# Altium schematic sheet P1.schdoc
size 297 x 209 mm; Symbol: Drawing-Symbol_A4; Company: 嘉立创EDA; Version: V1.0; Page Size: A4; @Project Name: Arduinoi时钟; @Update Date: 2026-04-30; @Create Date: 2026-04-30; Device: Drawing-Symbol_A4; @Board Name: Board1; @Page Name: P1; @Create Time: 08:59:18; @Page Count: 1; @Page No: 1; @Schematic Name: Schematic1; @Update Time: 08:59:18; @Assembly Variant: Basic; Border: 1; Title Block Position: 3; Size: A4; Width: 1170; Height: 825; Region Start: 1; X Region Count: 6; Y Region Count: 4; Blade Width: 10
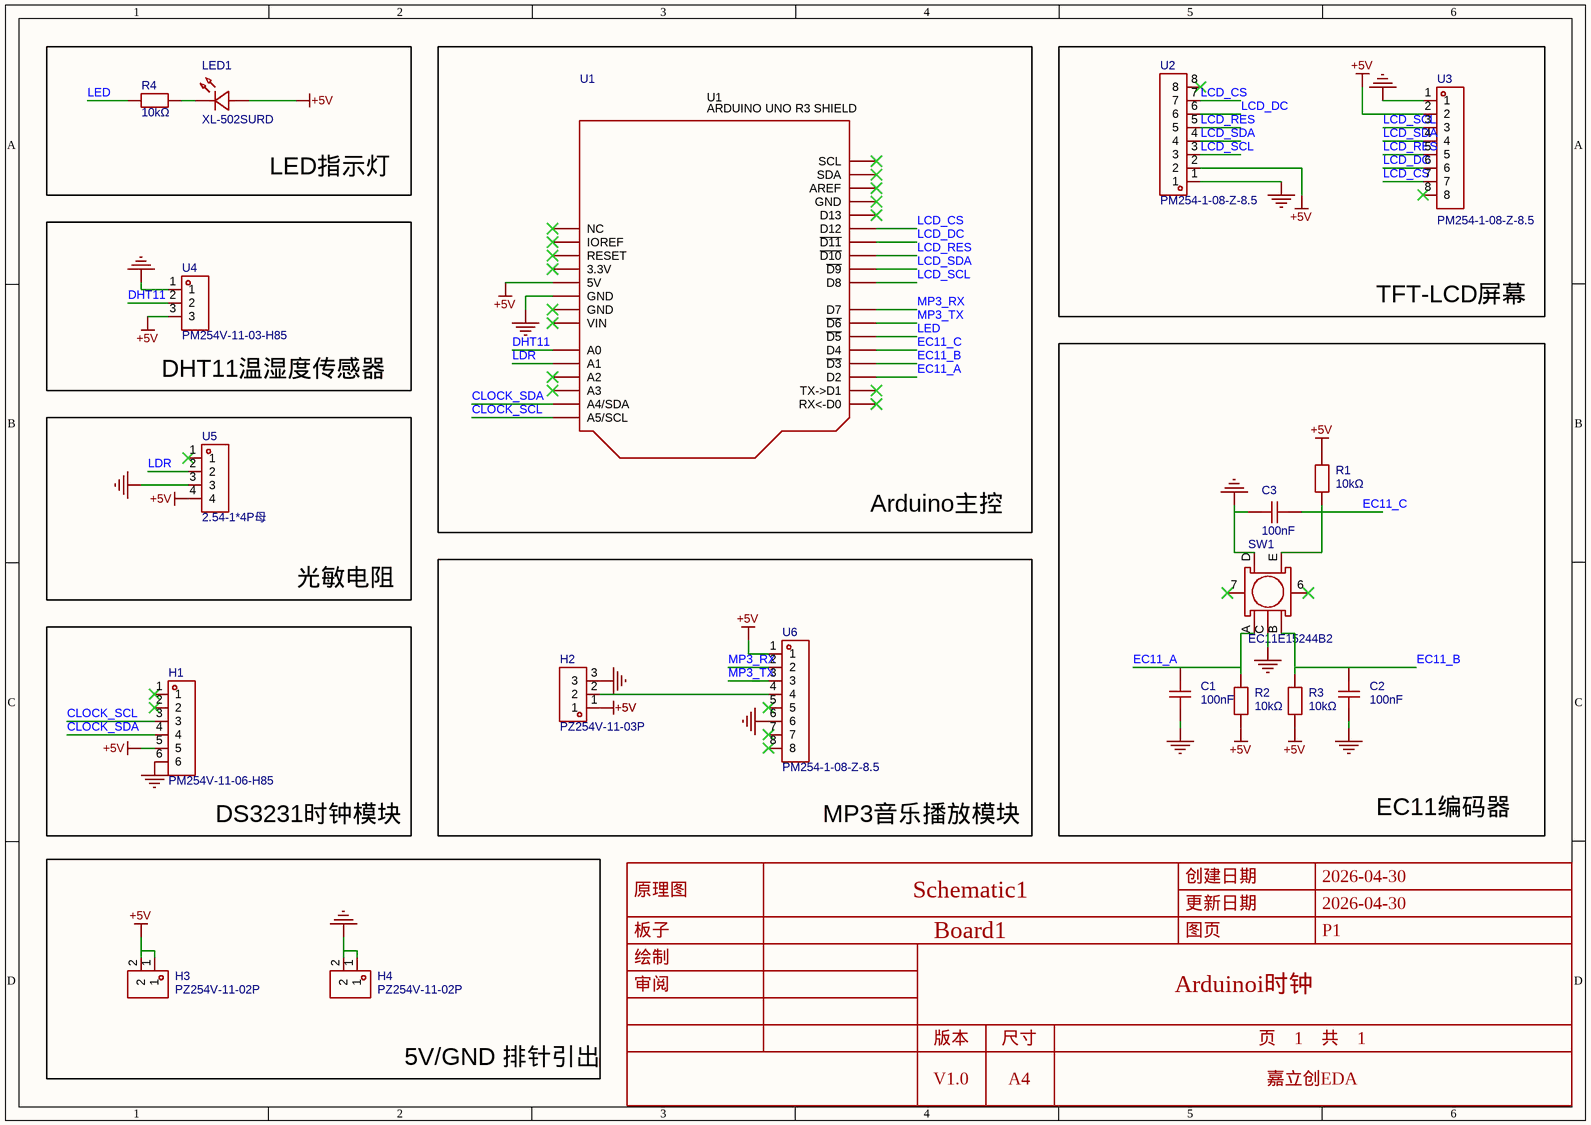
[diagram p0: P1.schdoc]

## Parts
C1  100nF  [CAP-TH_L6.5-W3.5-P5.00-D0.5]
C2  100nF  [CAP-TH_L6.5-W3.5-P5.00-D0.5]
C3  100nF  [CAP-TH_L6.5-W3.5-P5.00-D0.5]
H1  PM254V-11-06-H85  [HDR-TH_6P-P2.54-V-F]
H2  PZ254V-11-03P  [HDR-TH_3P-P2.54-V-M_PZ254V-11-03P]
H3  PZ254V-11-02P  [HDR-TH_2P-P2.54-V-M]
H4  PZ254V-11-02P  [HDR-TH_2P-P2.54-V-M]
LED1  XL-502SURD  [LED-TH_BD5.9-P2.54-RD_RED]
R1  10kΩ  [RES-TH_BD2.7-L6.2-P10.20-D0.4]
R2  10kΩ  [RES-TH_BD2.7-L6.2-P10.20-D0.4]
R3  10kΩ  [RES-TH_BD2.7-L6.2-P10.20-D0.4]
R4  10kΩ  [RES-TH_BD2.7-L6.2-P10.20-D0.4]
SW1  EC11E15244B2  [SW-TH_EC11XXXXXXXX]
U1  (no value)  [Arduino UNO]
U2  PM254-1-08-Z-8.5  [HDR-TH_8P-P2.54-V-F]
U3  PM254-1-08-Z-8.5  [HDR-TH_8P-P2.54-V-F]
U4  PM254V-11-03-H85  [HDR-TH_3P-P2.54-V-F]
U5  2.54-1*4P母  [HDR-TH_4P-P2.54-V-F]
U6  PM254-1-08-Z-8.5  [HDR-TH_8P-P2.54-V-F]

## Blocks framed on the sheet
LED指示灯: LED1 R4
Arduino主控: U1
TFT-LCD屏幕: U2 U3
DHT11温湿度传感器: U4
EC11编码器: C1-C3 R1-R3 SW1
光敏电阻: U5
MP3音乐播放模块: H2 U6
DS3231时钟模块: H1
5V/GND 排针引出: H3 H4

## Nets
+5V: H1.5 H2.1 H3.1 H3.2 LED1.2(A) R1.1 R2.1 R3.1 U1.22(5V) U2.2 U3.2 U4.3 U5.4 U6.1
GND: C1.1 C2.1 C3.2 H1.6 H2.3 H4.1 H4.2 SW1.C SW1.D U1.23(GND) U2.1 U3.1 U4.1 U5.3 U6.6
CLOCK_SCL: H1.3 U1.31(A5/SCL)
CLOCK_SDA: H1.4 U1.30(A4/SDA)
DHT11: U1.26(A0) U4.2
EC11_A: C1.2 R2.2 SW1.A U1.2(D2)
EC11_B: C2.2 R3.2 SW1.B U1.3(~{D3})
EC11_C: C3.1 R1.2 SW1.E U1.4(D4)
LCD_CS: U1.12(D12) U2.7 U3.7
LCD_DC: U1.11(~{D11}) U2.6 U3.6
LCD_RES: U1.10(~{D10}) U2.5 U3.5
LCD_SCL: U1.8(D8) U2.3 U3.3
LCD_SDA: U1.9(~{D9}) U2.4 U3.4
LDR: U1.27(A1) U5.2
LED: R4.2 U1.5(~{D5})
MP3_RX: U1.7(D7) U6.2
MP3_TX: U1.6(~{D6}) U6.3
NetH2_2: H2.2 U6.4
NetLED1_1: LED1.1(K) R4.1

Not connected (* = marked no-connect by the designer): H1 1* 2*; SW1 6* 7*; U1 0(RX<-D0)* 1(TX->D1)* 13(D13)* 14(GND)* 15(AREF)* 16(SDA)* 17(SCL)* 18(NC)* 19(IOREF)* 20(RESET)* 21(3.3V)* 24(GND)* 25(VIN)* 28(A2)* 29(A3)*; U2 8*; U3 8*; U5 1*; U6 5* 7* 8*

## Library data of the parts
C1-C3 = MPE104J100V82CL0044: 容值:100nF;精度:±5%;额定电压:100V;介电材料:金属化聚酯;工作温度:-55℃~+85℃;; Manufacturer: KNSCHA(科尼盛); Add into BOM: yes; 3D Model: 92b9490e7c4f40f8b38c7371d2623dc0; 3D Model Transform: 255.905,137.795,0,0,0,0,0,0,-590.551; Tolerance: ±5%; Voltage Rating: 100V; Dielectric Material: 金属化聚酯; ModelName: CAP-TH-2P-L6.5-W3.5-H8.0-P5.0
H1 = PM254V-11-06-H85: 插孔结构:1x6P;间距:2.54mm;行距:-;圆孔/方孔:方孔;安装方式:直插;排数:单排;总孔位数:6P;额定电流:3A;额定电压:250V;插孔方向:顶部;塑高:-;工作温度:-40℃~+105℃;; Manufacturer: XFCN(兴飞); AddInBom: yes; ModelId: 0f5bcf94dcda47d085f24cdca1696fe90819f05c4eef4c71ace90d822a990e87; ModelTransform: 619.684,94.488,0,0,0,0,0,0,-125.984; Holes Structure: 1x6P; Pitch: 2.54mm; Circular Hole / Square Hole: 方孔; Number of Positions: 6P; Current Rating: 3A; Voltage Rating (Max): 250V; Holes Direction: 顶部
H2 = PZ254V-11-03P: 插针结构:1x3P;间距:2.54mm;行距:-;圆针/方针:方针;安装方式:直插;排数:单排;总PIN位数:3P;额定电流:3A;额定电压:250V;配合针长度:6mm;塑高:2.5mm;端接针长度:3mm;工作温度:-40℃~+105℃;颜色:黑色;; Manufacturer: XFCN(兴飞); Symbol: PZ254V-11-03P_C2937625; AddInBom: yes; ModelId: bd28a638fbd247be9398fd5d39c366ec0819f05c4eef4c71ace90d822a990e87; ModelTransform: 300.3931,100,0,0,0,0,0,0,-118.11; Pin Structure: 1x3P; Pitch: 2.54mm; Circluar Pins/Square Pins: 方针; Current Rating: 3A; Voltage Rating (Max): 250V
H3 H4 = PZ254V-11-02P: 插针结构:1x2P;间距:2.54mm;行距:-;圆针/方针:方针;安装方式:直插;排数:单排;总PIN位数:2P;额定电流:3A;额定电压:250V;配合针长度:6mm;塑高:2.5mm;端接针长度:3mm;触头材质:黄铜;触头镀层:-;工作温度:-40℃~+105℃;颜色:黑色;; Manufacturer: XFCN(兴飞); AddInBom: yes; ModelId: e35305ec3aa84b66b849f914b715e73f0819f05c4eef4c71ace90d822a990e87; ModelName: HDR2.54-M-LI-1X2P; ModelTransform: 200,100,0,0,0,0,0,0,-118.11; Pin Structure: 1x2P; Pitch: 2.54mm; Circluar Pins/Square Pins: 方针; Current Rating: 3A; Voltage Rating (Max): 250V
LED1 = XL-502SURD: 灯头类型:5mm圆形灯头;发光颜色:红色;正向压降(Vf):2.4V;功率:70mW;正向电流:20mA;波长:615nm~625nm;二极管配置:-;透镜颜色:红色透镜;色温:-;发光强度:300mcd;发光角度:35°;载带方式:-;工作温度:-25℃~+85℃;; Manufacturer: XINGLIGHT(成兴光); AddInBom: yes; ModelId: fe9cea1bdf7642cd8d9a5077ed0e2b580819f05c4eef4c71ace90d822a990e87; ModelTransform: 211.96686,228.01584,0,0,0,0,7.874,0,-137.795; Illumination Color: 红色; Voltage - Forward(Vf): 2.4V; Power(Watts): 70mW; Forward Current: 20mA; Peak Wavelength: 654nm; Lens Color: 红色透镜; Luminous Intensity: 300mcd; Viewing Angle: 35°
R1 R4 = MF1/4W-10K±1%-ST52: 电阻类型:金属膜电阻;阻值:10kΩ;精度:±1%;功率:250mW;温度系数:±100ppm/℃;; Manufacturer: VO(翔胜); 3D Model: f91fbe0e2e6f409498f09f811e4616fe0819f05c4eef4c71ace90d822a990e87; 3D Model Transform: 417.322,106.221,0,0,0,0,0,0,-196.85; Tolerance: ±1%; Voltage-Supply(Max): 250V; Power(Watts): 250mW; AddInBom: yes
R2 R3 = MF1/4W-10K±1%-ST52: 电阻类型:金属膜电阻;阻值:10kΩ;精度:±1%;功率:250mW;温度系数:±100ppm/℃;; Manufacturer: VO(翔胜); AddInBom: yes; ModelId: f91fbe0e2e6f409498f09f811e4616fe0819f05c4eef4c71ace90d822a990e87; ModelTransform: 417.322,106.221,0,0,0,0,0,0,-196.85; Tolerance: ±1%; Voltage-Supply(Max): 250V; Power(Watts): 250mW
SW1 = EC11E15244B2_C470754: Manufacturer: ALPSALPINE(阿尔卑斯阿尔派); Add into BOM: yes; 3D Model: b9ea73ddb58141e1968840257f42eaba; 3D Model Transform: 495.18696,578.739,0,0,0,0,0,0,-137.795; ModelName: SW-TH_EC11XXXXXXXX-L11.7-W12.0-H24.5-P2.5-LS14.5
U1 = Arduino UNO: AddInBom: yes
U2 U3 U6 = PM254-1-08-Z-8.5: 插孔结构:1x8P;间距:2.54mm;行距:-;圆孔/方孔:方孔;安装方式:直插;排数:单排;总孔位数:8P;额定电流:3A;额定电压:-;插孔方向:顶部;塑高:8.5mm;触头材质:铜合金;工作温度:-40℃~+105℃;; Manufacturer: HCTL(华灿天禄); AddInBom: yes; ModelId: 6ab1dac21d924c3d8eea0dfa46d42ff50819f05c4eef4c71ace90d822a990e87; ModelTransform: 819.723,98.425,0,0,0,0,0,0,-118.11; Holes Structure: 1x8P; Pitch: 2.54mm; Circular Hole / Square Hole: 方孔; Number of Positions: 8P; Current Rating: 3A; Holes Direction: 顶部
U4 = PM254V-11-03-H85: 插孔结构:1x3P;间距:2.54mm;行距:-;圆孔/方孔:方孔;安装方式:直插;排数:单排;总孔位数:3P;额定电流:3A;插孔方向:顶部;塑高:8.5mm;触头材质:黄铜;触头镀层:-;工作温度:-40℃~+105℃;; Manufacturer: XFCN(兴飞); Add into BOM: yes; 3D Model: f3b3cc5aae9641bf9e56fc160cef875b; 3D Model Transform: 299.9994,100,0,0,0,0,0,0,-118.11; Holes Structure: 1x3P; Pitch: 2.54mm; Circular Hole / Square Hole: 方孔; Number of Positions: 3P; Current Rating: 3A; Holes Direction: 顶部; ModelName: HDR2.54-F-LI-1X3P
U5 = 2.54-1*4P母: 插孔结构:1x4P;间距:2.54mm;行距:-;圆孔/方孔:方孔;安装方式:直插;排数:单排;总孔位数:4P;额定电流:3A;额定电压:-;插孔方向:顶部;塑高:-;触头材质:青铜;触头镀层:-;工作温度:-40℃~+105℃;; Manufacturer: BOOMELE(博穆精密); Add into BOM: yes; 3D Model: d187812051054f85879fcaa51a310d8e; 3D Model Transform: 419.6842,98.464,0,0,0,0,0,0,-118.11; Holes Structure: 1x4P; Pitch: 2.54mm; Circular Hole / Square Hole: 方孔; Number of Positions: 4P; Current Rating: 3A; Holes Direction: 顶部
